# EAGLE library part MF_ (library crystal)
CRYSTAL FILTERS Source: http://www.presto.co.uk
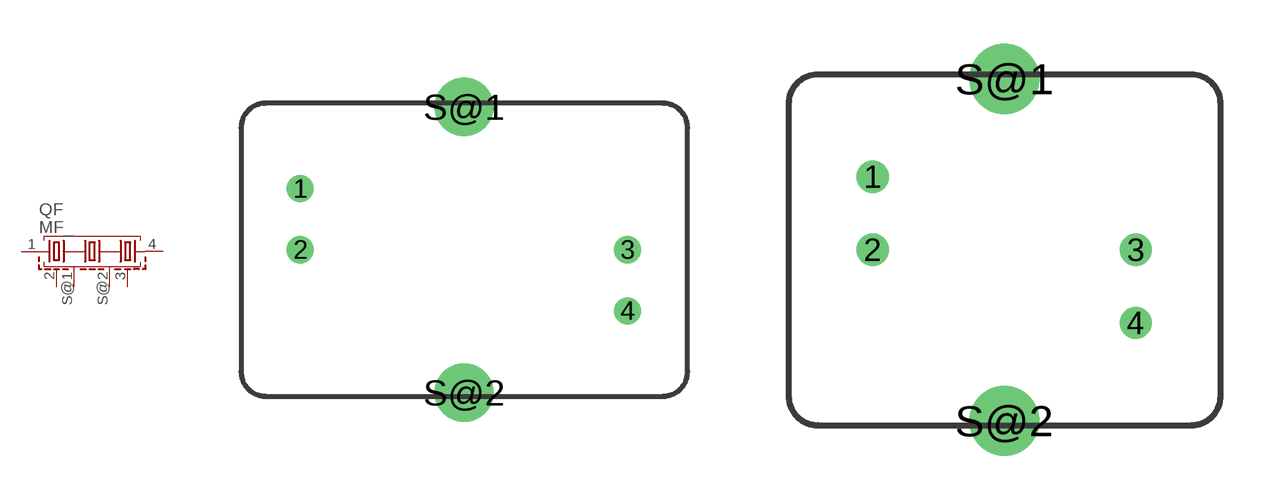
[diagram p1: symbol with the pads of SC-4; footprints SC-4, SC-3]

Designator prefix QF

## MF_10.7-12D (OC_FARNELL: unknown; OC_NEWARK: unknown)  [SC-4]
1  1  pas
2  2  pas
3  3  pas
4  4  pas
S@1  S  pas
S@2  S  pas

## MF_10.7-12C (OC_FARNELL: unknown; OC_NEWARK: unknown)  [SC-3]
Pads as for SC-4

## Footprint SC-4 (pad centres in mm)
CRYSTAL FILTERS Source: http://www.presto.co.uk
drill 0.6 pad 1.016 round: 1 -6.7,2.5; 2 -6.7,0; 3 6.7,0; 4 6.7,-2.5
drill 1.6 pad 1.93 round: S@1 0,5.85; S@2 0,-5.85

## Footprint SC-3 (pad centres in mm)
CRYSTAL FILTERS Source: http://www.presto.co.uk
drill 0.6 pad 1.016 round: 1 -4.5,2.5; 2 -4.5,0; 3 4.5,0; 4 4.5,-2.5
drill 1.6 pad 1.93 round: S@1 0,5.85; S@2 0,-5.85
